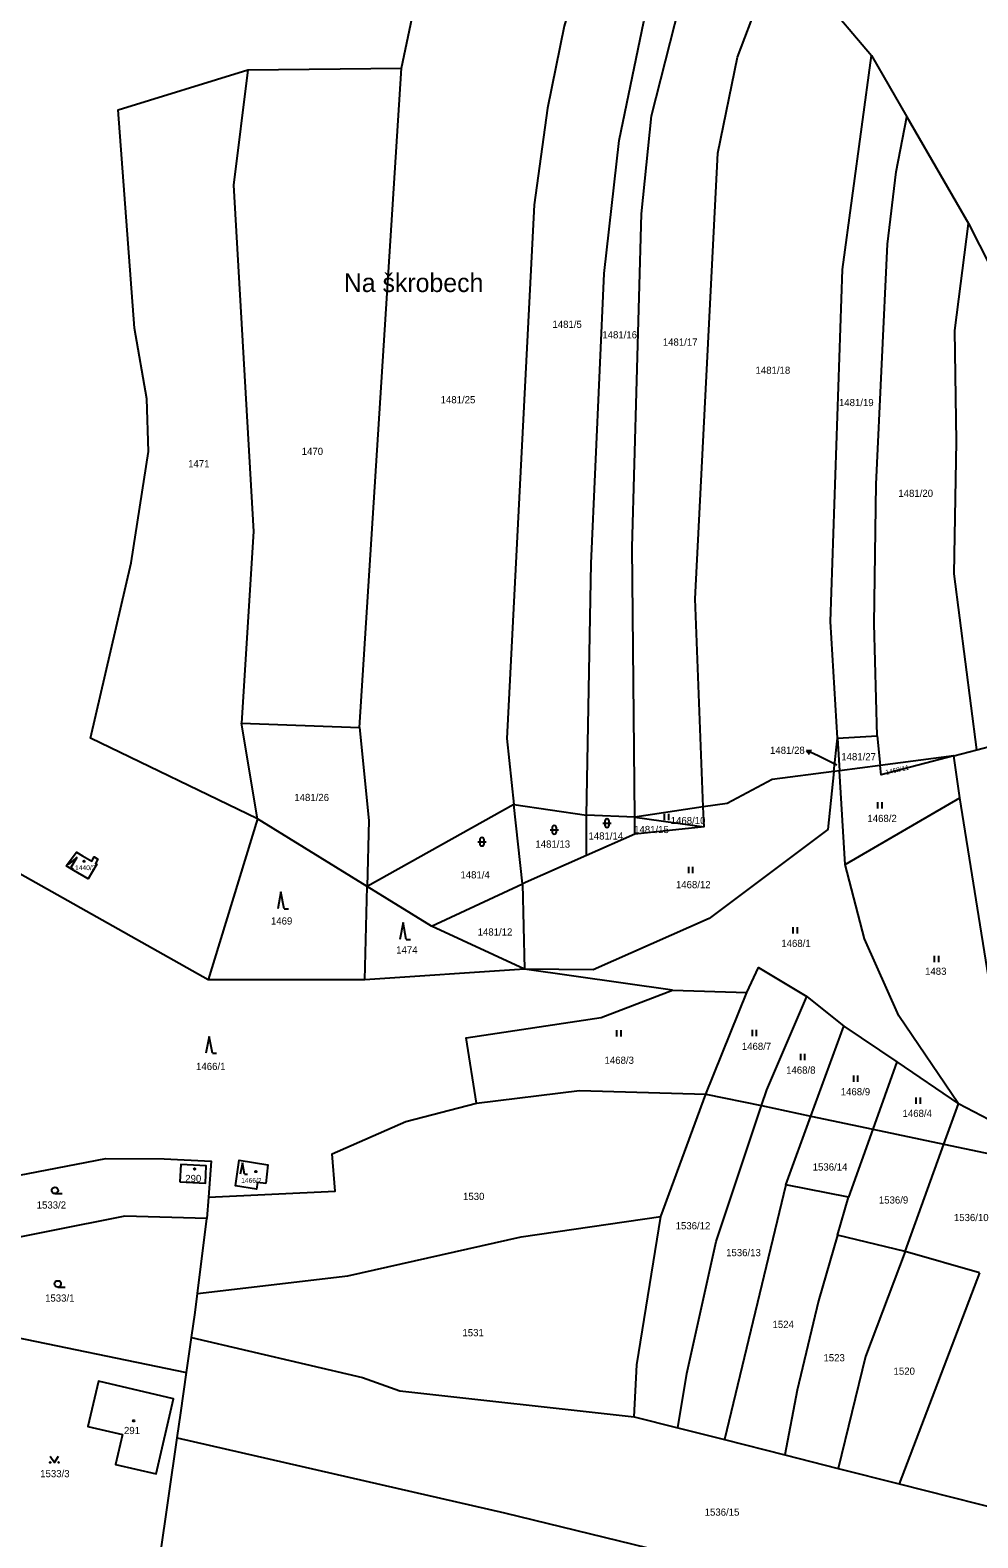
# Model space of a CAD drawing. Extents: x -725728 to -720881, y -1068679 to -1063504.
# Drawn here: x -723514.8 to -723290.5, y -1066402.9 to -1066046.1 of the extents above; entities that cross this region are included whole.
import ezdxf

# ---------------------------------------------------------------- set-up
doc = ezdxf.new("R2010")
doc.units = 0
for name, color, linetype in [('Hranice parcel', 7, 'Continuous'), ('Parcelní čísla', 7, 'Continuous'), ('Pop  PČ popisy', 7, 'Continuous'), ('Značky budov', 7, 'Continuous'), ('Značky kultur', 7, 'Continuous')]:
    doc.layers.add(name, color=color, linetype=linetype)

# ---------------------------------------------------------------- blocks, each defined once
blk = doc.blocks.new('4.02_3')
at = {"layer": 'Značky budov'}
blk.add_circle((-0.001, 0), 0.0175, dxfattribs=at)
blk = doc.blocks.new('4.02_7')
at = {"layer": 'Značky budov'}
blk.add_circle((0.001, 0), 0.0175, dxfattribs=at)
blk = doc.blocks.new('4.02_4')
at = {"layer": 'Značky budov'}
blk.add_circle((-0.001, 0), 0.0175, dxfattribs=at)
blk = doc.blocks.new('1029_166')
at = {"layer": 'Pop  PČ popisy'}
for p, q in [((-0.27, 0.131), (-0.158, 0.133)), ((0, 0), (-0.27, 0.131)), ((-0.27, 0.131), (-0.202, 0.042))]:
    blk.add_line(p, q, dxfattribs=at)
blk = doc.blocks.new('3.04_2')
at = {"layer": 'Značky kultur'}
blk.add_line((0.001, 0), (0.176, 0), dxfattribs=at)
blk.add_circle((0.001, 0.075), 0.075, dxfattribs=at)
blk = doc.blocks.new('3.14_1')
at = {"layer": 'Značky kultur'}
blk.add_lwpolyline([(-0.1, 0.15), (0, 0), (0.1, 0.15)], dxfattribs=at)
for centre in [(-0.1, 0), (0.1, 0)]:
    blk.add_circle(centre, 0.01, dxfattribs=at)
blk = doc.blocks.new('3.08_1')
at = {"layer": 'Značky kultur'}
for p, q in [((0, 0.4), (-0.075, 0)), ((0.075, 0), (0, 0.4)), ((0.075, 0), (0.175, 0))]:
    blk.add_line(p, q, dxfattribs=at)
blk = doc.blocks.new('3.08_4')
at = {"layer": 'Značky kultur'}
for p, q in [((0, 0.268), (-0.05, 0)), ((0.05, 0), (0, 0.268)), ((0.05, 0), (0.117, 0))]:
    blk.add_line(p, q, dxfattribs=at)
blk = doc.blocks.new('3.16_2')
at = {"layer": 'Značky kultur'}
for p, q in [((-0.1, 0.1), (0.1, 0.1)), ((-0.05, 0.15), (-0.05, 0.05)), ((0.05, 0.05), (0.05, 0.15))]:
    blk.add_line(p, q, dxfattribs=at)
for centre, start, end in [((0, 0.15), 0, 180), ((0, 0.05), 180, 359.9879)]:
    blk.add_arc(centre, 0.05, start, end, dxfattribs=at)
blk = doc.blocks.new('3.06_1')
at = {"layer": 'Značky kultur'}
for p, q in [((-0.051, 0), (-0.051, 0.15)), ((0.049, 0), (0.049, 0.15))]:
    blk.add_line(p, q, dxfattribs=at)
blk = doc.blocks.new('3.16_3')
at = {"layer": 'Značky kultur'}
for p, q in [((-0.1, 0.1), (0.1, 0.1)), ((-0.05, 0.15), (-0.05, 0.05)), ((0.05, 0.05), (0.05, 0.15))]:
    blk.add_line(p, q, dxfattribs=at)
for centre, start, end in [((0, 0.15), 0, 180), ((0, 0.05), 180, 359.9879)]:
    blk.add_arc(centre, 0.05, start, end, dxfattribs=at)
blk = doc.blocks.new('3.08_5')
at = {"layer": 'Značky kultur'}
for p, q in [((0.176, 0.202), (-0.038, 0.033)), ((0.038, -0.033), (0.176, 0.202)), ((0.038, -0.033), (0.088, -0.077))]:
    blk.add_line(p, q, dxfattribs=at)
blk = doc.blocks.new('3.06_2')
at = {"layer": 'Značky kultur'}
for p, q in [((-0.051, 0), (-0.051, 0.15)), ((0.049, 0), (0.049, 0.15))]:
    blk.add_line(p, q, dxfattribs=at)

msp = doc.modelspace()

# ---------------------------------------------------------------- linework, layer by layer
at = {"layer": 'Hranice parcel'}
for p, q in [((-723337.5, -1066026.3), (-723315.71, -1066052.14)), ((-723315.71, -1066052.14), (-723307.34, -1066066.63)), ((-723463.28, -1066055.52), (-723426.93, -1066055.14)), ((-723436.89, -1066211.17), (-723426.93, -1066055.14)), ((-723307.34, -1066066.63), (-723292.77, -1066091.87)), ((-723292.77, -1066091.87), (-723280.22, -1066116.65)), ((-723461.05, -1066232.77), (-723464.77, -1066210.15)), ((-723464.77, -1066210.15), (-723436.89, -1066211.17)), ((-723323.77, -1066213.71), (-723314.32, -1066213.11)), ((-723314.32, -1066213.11), (-723313.62, -1066220.15)), ((-723290.75, -1066216.46), (-723267.33, -1066210.31)), ((-723324.59, -1066221.57), (-723323.77, -1066213.71)), ((-723323.77, -1066213.71), (-723323.3, -1066221.4)), ((-723296.24, -1066217.9), (-723290.75, -1066216.46)), ((-723313.62, -1066220.15), (-723323.3, -1066221.4)), ((-723296.24, -1066217.9), (-723313.62, -1066220.15)), ((-723294.76, -1066227.83), (-723296.24, -1066217.9)), ((-723323.3, -1066221.4), (-723324.59, -1066221.57)), ((-723321.94, -1066243.58), (-723323.3, -1066221.4)), ((-723400.33, -1066229.43), (-723435.08, -1066248.8)), ((-723398.33, -1066248.19), (-723400.33, -1066229.43)), ((-723400.33, -1066229.43), (-723383.14, -1066231.96)), ((-723355.51, -1066229.98), (-723371.74, -1066232.43)), ((-723355.32, -1066234.71), (-723355.51, -1066229.98)), ((-723321.94, -1066243.58), (-723294.76, -1066227.83)), ((-723461.05, -1066232.77), (-723472.65, -1066270.88)), ((-723435.08, -1066248.8), (-723461.05, -1066232.77)), ((-723371.74, -1066232.43), (-723383.14, -1066231.96)), ((-723383.14, -1066241.48), (-723383.14, -1066231.96)), ((-723371.7, -1066236.43), (-723371.74, -1066232.43)), ((-723371.74, -1066232.43), (-723355.32, -1066234.71)), ((-723355.32, -1066234.71), (-723371.7, -1066236.43)), ((-723472.65, -1066270.88), (-723536.02, -1066235.3)), ((-723371.7, -1066236.43), (-723383.14, -1066241.48)), ((-723383.14, -1066241.48), (-723398.33, -1066248.19)), ((-723435.64, -1066270.91), (-723435.08, -1066248.8)), ((-723419.82, -1066258.22), (-723435.08, -1066248.8)), ((-723419.82, -1066258.22), (-723398.33, -1066248.19)), ((-723398.33, -1066248.19), (-723397.8, -1066268.35)), ((-723397.8, -1066268.35), (-723419.82, -1066258.22)), ((-723397.8, -1066268.35), (-723435.64, -1066270.91)), ((-723362.79, -1066273.37), (-723397.8, -1066268.35)), ((-723435.64, -1066270.91), (-723472.65, -1066270.88)), ((-723362.79, -1066273.37), (-723345.21, -1066273.92)), ((-723354.87, -1066297.92), (-723345.21, -1066273.92)), ((-723330.99, -1066274.81), (-723322.25, -1066281.88)), ((-723330.04, -1066303.13), (-723322.25, -1066281.88)), ((-723322.25, -1066281.88), (-723309.69, -1066290.31)), ((-723309.69, -1066290.31), (-723315.37, -1066306.21)), ((-723309.69, -1066290.31), (-723295.14, -1066300.27)), ((-723365.53, -1066326.9), (-723354.87, -1066297.92)), ((-723354.87, -1066297.92), (-723341.76, -1066300.67)), ((-723341.76, -1066300.67), (-723330.04, -1066303.13)), ((-723298.56, -1066309.75), (-723295.14, -1066300.27)), ((-723275.08, -1066310.68), (-723295.14, -1066300.27)), ((-723336, -1066319.41), (-723330.04, -1066303.13)), ((-723330.04, -1066303.13), (-723315.37, -1066306.21)), ((-723315.37, -1066306.21), (-723321.13, -1066322.34)), ((-723315.37, -1066306.21), (-723298.56, -1066309.75)), ((-723307.71, -1066335.16), (-723298.56, -1066309.75)), ((-723298.56, -1066309.75), (-723276.9, -1066314.3)), ((-723336, -1066319.41), (-723350.48, -1066379.71)), ((-723321.13, -1066322.34), (-723336, -1066319.41)), ((-723472.61, -1066322.31), (-723472.98, -1066327.41)), ((-723323.73, -1066331.34), (-723321.13, -1066322.34)), ((-723475.2, -1066345.1), (-723472.98, -1066327.41)), ((-723307.71, -1066335.16), (-723323.73, -1066331.34)), ((-723290.16, -1066340.27), (-723307.71, -1066335.16)), ((-723290.16, -1066340.27), (-723309.18, -1066390.15)), ((-723543.73, -1066350.16), (-723477.82, -1066363.84)), ((-723477.82, -1066363.84), (-723476.62, -1066355.51)), ((-723371.86, -1066374.3), (-723361.53, -1066376.91)), ((-723361.53, -1066376.91), (-723350.48, -1066379.71)), ((-723484.09, -1066407.85), (-723480.03, -1066379.32)), ((-723350.48, -1066379.71), (-723336.2, -1066383.32)), ((-723336.2, -1066383.32), (-723323.57, -1066386.51)), ((-723323.57, -1066386.51), (-723309.18, -1066390.15)), ((-723309.18, -1066390.15), (-723284.22, -1066396.46))]:
    msp.add_line(p, q, dxfattribs=at)
for points in [[(-723426.93, -1066055.14), (-723422.43, -1066033.67), (-723418.52, -1066019.12), (-723406.08, -1065988.8)], [(-723368.89, -1065989.07), (-723379.88, -1066016.49), (-723388.4, -1066045.2), (-723392.35, -1066064.63), (-723395.56, -1066087.47), (-723401.99, -1066213.79), (-723400.33, -1066229.43)], [(-723383.14, -1066231.96), (-723382.01, -1066172.39), (-723378.99, -1066103.76), (-723375.4, -1066072.24), (-723369.57, -1066044.08), (-723355.45, -1066005.01)], [(-723371.74, -1066232.43), (-723372.37, -1066168.46), (-723370.13, -1066089.65), (-723367.78, -1066066.43), (-723361.16, -1066040.41), (-723349.59, -1066011.96)], [(-723355.51, -1066229.98), (-723357.45, -1066180.76), (-723352.08, -1066075.29), (-723347.37, -1066052.52), (-723337.5, -1066026.3)], [(-723323.77, -1066213.71), (-723325.42, -1066186.09), (-723322.56, -1066102.78), (-723315.71, -1066052.14)], [(-723461.05, -1066232.77), (-723500.53, -1066213.71), (-723490.89, -1066172.21), (-723486.78, -1066145.86), (-723487.17, -1066133.4), (-723490.12, -1066116.69), (-723493.97, -1066065.03), (-723463.28, -1066055.52)], [(-723463.28, -1066055.52), (-723466.73, -1066082.79), (-723461.97, -1066164.8), (-723464.77, -1066210.15)], [(-723314.32, -1066213.11), (-723315.07, -1066186.64), (-723314.62, -1066153.59), (-723311.92, -1066096.81), (-723309.82, -1066079.69), (-723307.34, -1066066.63)], [(-723290.75, -1066216.46), (-723296.15, -1066174.83), (-723295.55, -1066143.46), (-723296, -1066117.19), (-723292.77, -1066091.87)], [(-723436.89, -1066211.17), (-723434.68, -1066233.16), (-723435.08, -1066248.8)], [(-723296.24, -1066217.9), (-723313.4, -1066222.41), (-723313.62, -1066220.15)], [(-723324.59, -1066221.57), (-723326.02, -1066235.32), (-723354.08, -1066256.34), (-723381.53, -1066268.5), (-723397.8, -1066268.35)], [(-723324.59, -1066221.57), (-723339.24, -1066223.47), (-723349.87, -1066229.13), (-723355.51, -1066229.98)], [(-723275.08, -1066310.68), (-723287.72, -1066272.16), (-723294.76, -1066227.83)], [(-723506.27, -1066243.93), (-723503.81, -1066240.66), (-723502.41, -1066241.56), (-723500.23, -1066242.84), (-723499.63, -1066241.82), (-723498.79, -1066242.31), (-723499.37, -1066243.33), (-723499.04, -1066243.53), (-723501.08, -1066246.95), (-723504.47, -1066245.01), (-723506.27, -1066243.93)], [(-723295.14, -1066300.27), (-723309.23, -1066279.43), (-723317.35, -1066261.2), (-723321.94, -1066243.58)], [(-723345.21, -1066273.92), (-723342.46, -1066267.94), (-723330.99, -1066274.81)], [(-723409.16, -1066300.1), (-723411.63, -1066284.63), (-723379.71, -1066279.84), (-723362.79, -1066273.37)], [(-723341.76, -1066300.67), (-723340.5, -1066296.89), (-723330.99, -1066274.81)], [(-723409.16, -1066300.1), (-723384.79, -1066297.1), (-723354.87, -1066297.92)], [(-723472.61, -1066322.31), (-723442.66, -1066320.93), (-723443.34, -1066312.07), (-723425.94, -1066304.41), (-723409.16, -1066300.1)], [(-723361.53, -1066376.91), (-723359.41, -1066364.09), (-723352.45, -1066332.85), (-723341.76, -1066300.67)], [(-723529.28, -1066319.44), (-723496.9, -1066313.16), (-723483.13, -1066313.27), (-723472.01, -1066313.77), (-723472.61, -1066322.31)], [(-723479.36, -1066318.69), (-723473.34, -1066318.98), (-723473.15, -1066314.91), (-723479.17, -1066314.63), (-723479.36, -1066318.69)], [(-723459.02, -1066319.11), (-723461.02, -1066318.86), (-723461.23, -1066320.4), (-723466.21, -1066319.67), (-723465.34, -1066313.6), (-723458.54, -1066314.65), (-723459.02, -1066319.11)], [(-723472.98, -1066327.41), (-723492.44, -1066326.79), (-723527.77, -1066333.84), (-723541.37, -1066336.55)], [(-723475.2, -1066345.1), (-723439.6, -1066340.98), (-723398.62, -1066331.75), (-723365.53, -1066326.9)], [(-723371.86, -1066374.3), (-723371.25, -1066361.97), (-723365.53, -1066326.9)], [(-723323.73, -1066331.34), (-723328.2, -1066346.87), (-723333.32, -1066367.97), (-723336.2, -1066383.32)], [(-723307.71, -1066335.16), (-723317.1, -1066360.04), (-723323.57, -1066386.51)], [(-723476.62, -1066355.51), (-723475.77, -1066349.61), (-723475.2, -1066345.1)], [(-723476.62, -1066355.51), (-723436.17, -1066365.04), (-723427.3, -1066368.14), (-723371.86, -1066374.3)], [(-723492.97, -1066378.51), (-723494.61, -1066385.59), (-723484.99, -1066387.83), (-723480.86, -1066370.03), (-723498.66, -1066365.9), (-723501.15, -1066376.61), (-723492.97, -1066378.51)], [(-723480.03, -1066379.32), (-723479.19, -1066373.4), (-723477.82, -1066363.84)], [(-723480.03, -1066379.32), (-723402.59, -1066397.02), (-723324.97, -1066415.98), (-723259.55, -1066434.36)]]:
    msp.add_lwpolyline(points, dxfattribs=at)
at = {"layer": 'Pop  PČ popisy'}
msp.add_line((-723323.89, -1066220.11), (-723328.34, -1066217.9), dxfattribs=at)

# ---------------------------------------------------------------- block references
at = {"layer": 'Pop  PČ popisy', "xscale": 10, "yscale": 10}
msp.add_blockref('1029_166', (-723328.34, -1066217.9), dxfattribs=at)
at = {"layer": 'Značky budov', "xscale": 10, "yscale": 10}
for name, p in [('4.02_7', (-723502.06, -1066242.82)), ('4.02_4', (-723475.89, -1066315.66)), ('4.02_3', (-723461.4, -1066316.27)), ('4.02_3', (-723490.3, -1066375.26))]:
    msp.add_blockref(name, p, dxfattribs=at)
at = {"layer": 'Značky kultur', "xscale": 10, "yscale": 10}
for name, p in [('3.06_1', (-723313.68, -1066230.37)), ('3.16_3', (-723390.78, -1066236.4)), ('3.16_2', (-723378.3, -1066234.81)), ('3.06_1', (-723364.16, -1066233.12)), ('3.16_2', (-723407.9, -1066239.21)), ('3.08_5', (-723505.48, -1066243.91)), ('3.06_1', (-723358.44, -1066245.61)), ('3.08_1', (-723455.45, -1066254.07)), ('3.08_1', (-723426.57, -1066261.35)), ('3.06_2', (-723333.73, -1066259.9)), ('3.06_1', (-723300.25, -1066266.73)), ('3.08_1', (-723472.45, -1066288.27)), ('3.06_1', (-723375.45, -1066284.27)), ('3.06_1', (-723343.37, -1066284.26)), ('3.06_1', (-723331.93, -1066289.94)), ('3.06_1', (-723319.39, -1066295.02)), ('3.06_1', (-723304.61, -1066300.22)), ('3.08_4', (-723464.58, -1066316.9)), ('3.04_2', (-723508.97, -1066321.48)), ('3.04_2', (-723508.29, -1066343.59)), ('3.14_1', (-723509.07, -1066385.1))]:
    msp.add_blockref(name, p, dxfattribs=at)

# ---------------------------------------------------------------- texts
at = {"layer": 'Parcelní čísla'}
for s, height, p in [('1481/5', 1.7, (-723391.21, -1066116.61)), ('1481/16', 1.7, (-723379.4, -1066119.08)), ('1481/17', 1.7, (-723365.09, -1066120.81)), ('1481/18', 1.7, (-723343.14, -1066127.47)), ('1481/25', 1.7, (-723417.67, -1066134.45)), ('1481/19', 1.7, (-723323.4, -1066135.12)), ('1470', 1.7, (-723450.55, -1066146.67)), ('1471', 1.7, (-723477.43, -1066149.6)), ('1481/20', 1.7, (-723309.34, -1066156.6)), ('1481/28', 1.7, (-723339.71, -1066217.41)), ('1481/27', 1.7, (-723322.85, -1066218.94)), ('1481/26', 1.7, (-723452.3, -1066228.58)), ('1481/15', 1.7, (-723371.87, -1066236.16)), ('1468/10', 1.7, (-723363.21, -1066234.04)), ('1468/2', 1.7, (-723316.66, -1066233.54)), ('1481/13', 1.7, (-723395.24, -1066239.61)), ('1481/14', 1.7, (-723382.68, -1066237.69)), ('1440/2', 1.14, (-723504.18, -1066244.93)), ('1481/4', 1.7, (-723412.98, -1066246.89)), ('1468/12', 1.7, (-723361.98, -1066249.21)), ('1469', 1.7, (-723457.83, -1066257.81)), ('1481/12', 1.7, (-723408.91, -1066260.42)), ('1474', 1.7, (-723428.18, -1066264.66)), ('1468/1', 1.7, (-723337.04, -1066263.11)), ('1483', 1.7, (-723303.01, -1066269.7)), ('1468/7', 1.7, (-723346.38, -1066287.48)), ('1466/1', 1.7, (-723475.55, -1066292.23)), ('1468/3', 1.7, (-723378.87, -1066290.77)), ('1468/8', 1.7, (-723335.9, -1066293.1)), ('1468/9', 1.7, (-723322.97, -1066298.22)), ('1468/4', 1.7, (-723308.34, -1066303.34)), ('1536/14', 1.7, (-723329.61, -1066316.03)), ('290', 1.7, (-723478.11, -1066318.75)), ('1466/2', 1.14, (-723464.87, -1066318.94)), ('1533/2', 1.7, (-723513.27, -1066325.03)), ('1530', 1.7, (-723412.36, -1066322.99)), ('1536/9', 1.7, (-723313.95, -1066323.84)), ('1536/10', 1.7, (-723296.19, -1066327.99)), ('1536/12', 1.7, (-723362.05, -1066329.94)), ('1536/13', 1.7, (-723350.1, -1066336.29)), ('1533/1', 1.7, (-723511.28, -1066347.05)), ('1524', 1.7, (-723339.12, -1066353.28)), ('1531', 1.7, (-723412.51, -1066355.24)), ('1523', 1.7, (-723327.06, -1066361.18)), ('1520', 1.7, (-723310.47, -1066364.35)), ('291', 1.7, (-723492.61, -1066378.39)), ('1533/3', 1.7, (-723512.44, -1066388.6)), ('1536/15', 1.7, (-723355.18, -1066397.71))]:
    msp.add_text(s, height=height, dxfattribs=at).set_placement(p)
msp.add_text('1468/11', height=1.139, rotation=13, dxfattribs=at).set_placement((-723312.24, -1066222.39))
at = {"layer": 'Pop  PČ popisy'}
msp.add_text('Na škrobech', height=4.4, dxfattribs=at).set_placement((-723440.58, -1066108.12))

doc.saveas('drawing.dxf')
